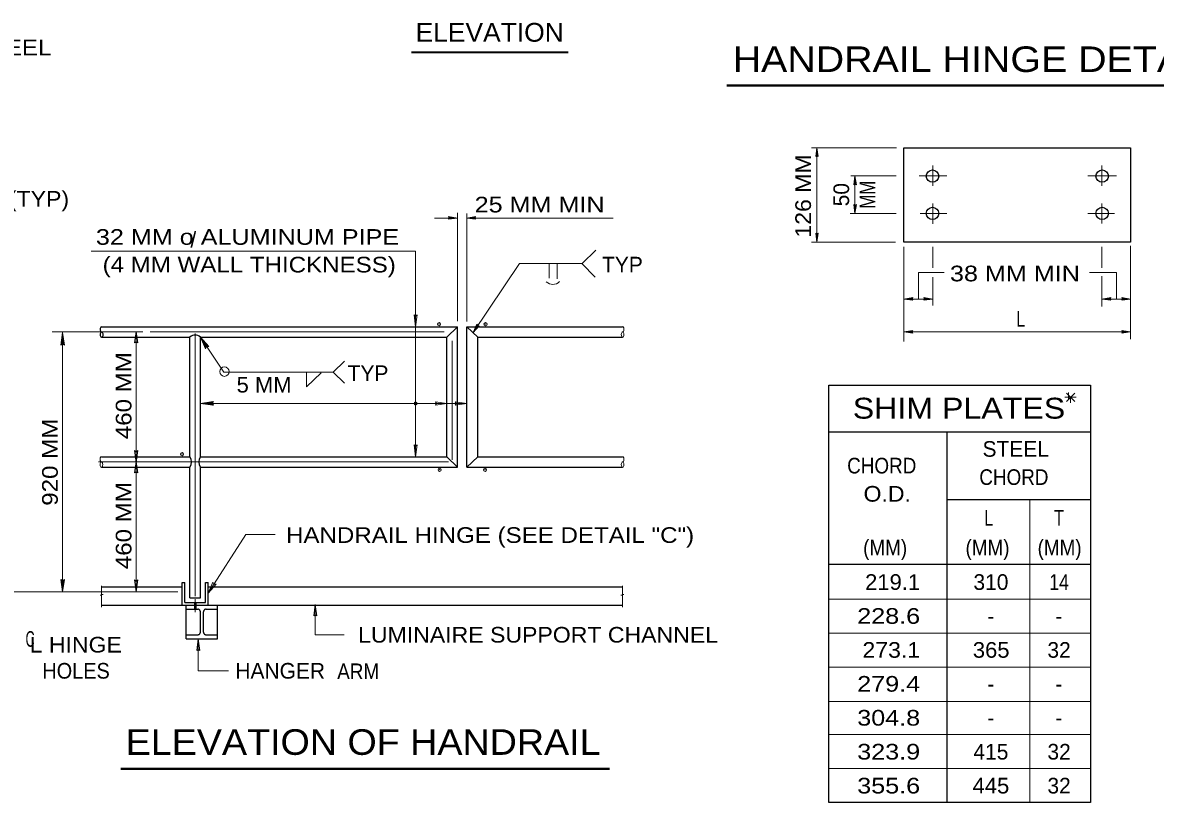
# Model space of a CAD drawing. Extents: x 312601.858 to 312602.699, y 144420.109 to 144420.704.
# Drawn here: x 312602.2633 to 312602.4801, y 144420.4036 to 144420.553 of the extents above; entities that cross this region are included whole.
import ezdxf
from ezdxf.enums import TextEntityAlignment as Align

# ---------------------------------------------------------------- set-up
doc = ezdxf.new("R2010")
doc.units = 0
doc.header["$LTSCALE"] = 0.0012
doc.header["$PDMODE"] = 32
doc.header["$PDSIZE"] = 0.0006
doc.linetypes.add('DOT_DASHED', pattern=[7.7, 5, -1.2, 0.3, -1.2])
doc.linetypes.add('LONG_DASHED', pattern=[7.5, 6, -1.5])
for name, color, linetype, lineweight in [('1', 7, 'Continuous', 13), ('2', 7, 'Continuous', 13), ('39', 7, 'Continuous', 13)]:
    doc.layers.add(name, color=color, linetype=linetype, lineweight=lineweight)

msp = doc.modelspace()

# ---------------------------------------------------------------- hatches: boundary and pattern name
at = {"layer": '2'}
msp.add_hatch(color=256, dxfattribs=at).paths.add_polyline_path([(312602.3388, 144420.48, 1), (312602.3382, 144420.48, 1)])
at = {"layer": '39'}
for points in [[(312602.4153, 144420.5275), (312602.4151, 144420.5273), (312602.4153, 144420.529), (312602.4156, 144420.5273)], [(312602.4153, 144420.5275), (312602.4151, 144420.5273), (312602.4153, 144420.529), (312602.4156, 144420.5273)], [(312602.4226, 144420.5221), (312602.4224, 144420.5219), (312602.4226, 144420.5236), (312602.4229, 144420.5219)], [(312602.4226, 144420.518), (312602.4229, 144420.5181), (312602.4226, 144420.5164), (312602.4224, 144420.5181)], [(312602.4226, 144420.518), (312602.4229, 144420.5181), (312602.4226, 144420.5164), (312602.4224, 144420.5181)], [(312602.345, 144420.5155), (312602.3448, 144420.5158), (312602.3465, 144420.5155), (312602.3448, 144420.5153)], [(312602.3499, 144420.5155), (312602.35, 144420.5153), (312602.3483, 144420.5155), (312602.35, 144420.5158)], [(312602.4153, 144420.5125), (312602.4156, 144420.5126), (312602.4153, 144420.5109), (312602.4151, 144420.5126)], [(312602.4153, 144420.5125), (312602.4156, 144420.5126), (312602.4153, 144420.5109), (312602.4151, 144420.5126)], [(312602.4336, 144420.5), (312602.4337, 144420.4998), (312602.432, 144420.5), (312602.4337, 144420.5003)], [(312602.436, 144420.5), (312602.4358, 144420.5003), (312602.4375, 144420.5), (312602.4358, 144420.4998)], [(312602.436, 144420.5), (312602.4358, 144420.5003), (312602.4375, 144420.5), (312602.4358, 144420.4998)], [(312602.4715, 144420.5), (312602.4716, 144420.4998), (312602.4699, 144420.5), (312602.4716, 144420.5003)], [(312602.4739, 144420.5), (312602.4737, 144420.5003), (312602.4754, 144420.5), (312602.4737, 144420.4998)], [(312602.3504, 144420.4949), (312602.3507, 144420.4949), (312602.3495, 144420.4936), (312602.3502, 144420.4952)], [(312602.4336, 144420.4937), (312602.4337, 144420.4935), (312602.432, 144420.4937), (312602.4337, 144420.494)], [(312602.4739, 144420.4937), (312602.4737, 144420.494), (312602.4754, 144420.4937), (312602.4737, 144420.4935)], [(312602.2709, 144420.4914), (312602.2706, 144420.4912), (312602.2709, 144420.4936), (312602.2713, 144420.4912)], [(312602.2709, 144420.4914), (312602.2706, 144420.4912), (312602.2709, 144420.4936), (312602.2713, 144420.4912)], [(312602.2985, 144420.4909), (312602.2983, 144420.4905), (312602.2973, 144420.4927), (312602.2989, 144420.4909)], [(312602.2995, 144420.48), (312602.2997, 144420.4797), (312602.2973, 144420.48), (312602.2997, 144420.4804)], [(312602.2996, 144420.48), (312602.2998, 144420.4797), (312602.2974, 144420.48), (312602.2998, 144420.4804)], [(312602.2709, 144420.4461), (312602.2713, 144420.4463), (312602.2709, 144420.4439), (312602.2706, 144420.4463)]]:
    msp.add_hatch(color=256, dxfattribs=at).paths.add_polyline_path(points)

# ---------------------------------------------------------------- linework, layer by layer
at = {"layer": '1'}
for p, q in [((312602.4143, 144420.529), (312602.4306, 144420.529)), ((312602.4153, 144420.529), (312602.4153, 144420.5109)), ((312602.4218, 144420.5236), (312602.4305, 144420.5236)), ((312602.4226, 144420.5236), (312602.4226, 144420.5164)), ((312602.3421, 144420.5155), (312602.3465, 144420.5155)), ((312602.3465, 144420.4958), (312602.3465, 144420.5165)), ((312602.3483, 144420.4957), (312602.3483, 144420.5164)), ((312602.3483, 144420.5155), (312602.3763, 144420.5155)), ((312602.4217, 144420.5164), (312602.4305, 144420.5164)), ((312602.2764, 144420.5092), (312602.3385, 144420.5092)), ((312602.3385, 144420.5092), (312602.3385, 144420.4947)), ((312602.4304, 144420.5109), (312602.4143, 144420.5109)), ((312602.432, 144420.4919), (312602.432, 144420.51)), ((312602.4375, 144420.51), (312602.4375, 144420.506)), ((312602.4699, 144420.51), (312602.4699, 144420.506)), ((312602.4754, 144420.5102), (312602.4754, 144420.4923)), ((312602.3641, 144420.504), (312602.3641, 144420.5068)), ((312602.3656, 144420.5039), (312602.3656, 144420.5068)), ((312602.4375, 144420.5042), (312602.4375, 144420.4988)), ((312602.4699, 144420.5044), (312602.4699, 144420.4986)), ((312602.432, 144420.5), (312602.4375, 144420.5)), ((312602.4699, 144420.5), (312602.4754, 144420.5)), ((312602.3385, 144420.4947), (312602.3385, 144420.4698)), ((312602.2689, 144420.4937), (312602.2863, 144420.4937)), ((312602.2709, 144420.4936), (312602.2709, 144420.4439)), ((312602.285, 144420.4937), (312602.285, 144420.4439)), ((312602.432, 144420.4937), (312602.4754, 144420.4937)), ((312602.4561, 144420.4616), (312602.4561, 144420.4036)), ((312602.2988, 144420.4437), (312602.306, 144420.4549)), ((312602.306, 144420.4549), (312602.3116, 144420.4549)), ((312602.254, 144420.4439), (312602.293, 144420.4439)), ((312602.4677, 144420.4425), (312602.4176, 144420.4425)), ((312602.4677, 144420.436), (312602.4176, 144420.436)), ((312602.2969, 144420.4349), (312602.2969, 144420.4288)), ((312602.3027, 144420.4288), (312602.2969, 144420.4288)), ((312602.4677, 144420.4295), (312602.4176, 144420.4295)), ((312602.4677, 144420.4229), (312602.4176, 144420.4229)), ((312602.4677, 144420.4166), (312602.4176, 144420.4166)), ((312602.4677, 144420.4101), (312602.4176, 144420.4101))]:
    msp.add_line(p, q, dxfattribs=at)
at = {"layer": '1', "lineweight": 25}
for p, q in [((312602.432, 144420.529), (312602.4754, 144420.529)), ((312602.432, 144420.5109), (312602.432, 144420.529)), ((312602.4754, 144420.529), (312602.4754, 144420.5109)), ((312602.4754, 144420.5109), (312602.432, 144420.5109)), ((312602.2784, 144420.4947), (312602.2938, 144420.4947)), ((312602.2937, 144420.4947), (312602.3465, 144420.4947)), ((312602.3465, 144420.4678), (312602.3465, 144420.4947)), ((312602.3483, 144420.4947), (312602.3781, 144420.4947)), ((312602.3483, 144420.4678), (312602.3483, 144420.4947)), ((312602.2784, 144420.4927), (312602.2953, 144420.4927)), ((312602.2953, 144420.4698), (312602.2953, 144420.4927)), ((312602.2973, 144420.4927), (312602.3445, 144420.4927)), ((312602.2973, 144420.4698), (312602.2973, 144420.4927)), ((312602.3445, 144420.4698), (312602.3445, 144420.4927)), ((312602.3504, 144420.4927), (312602.3781, 144420.4927)), ((312602.3504, 144420.4698), (312602.3504, 144420.4927)), ((312602.4176, 144420.4835), (312602.4677, 144420.4835)), ((312602.4176, 144420.4036), (312602.4176, 144420.4835)), ((312602.4176, 144420.4746), (312602.4677, 144420.4746)), ((312602.4402, 144420.4746), (312602.4402, 144420.4036)), ((312602.2784, 144420.4698), (312602.2953, 144420.4698)), ((312602.2784, 144420.4678), (312602.2953, 144420.4678)), ((312602.2953, 144420.4428), (312602.2953, 144420.4678)), ((312602.2973, 144420.4698), (312602.3445, 144420.4698)), ((312602.2973, 144420.4678), (312602.3465, 144420.4678)), ((312602.2973, 144420.4428), (312602.2973, 144420.4678)), ((312602.3483, 144420.4678), (312602.3781, 144420.4678)), ((312602.3504, 144420.4698), (312602.3781, 144420.4698)), ((312602.4402, 144420.4616), (312602.4677, 144420.4616)), ((312602.4176, 144420.4492), (312602.4677, 144420.4492)), ((312602.2784, 144420.4449), (312602.2938, 144420.4449)), ((312602.2938, 144420.4457), (312602.2943, 144420.4457)), ((312602.2938, 144420.4414), (312602.2938, 144420.4457)), ((312602.2943, 144420.4419), (312602.2943, 144420.4457)), ((312602.2983, 144420.4457), (312602.2988, 144420.4457)), ((312602.2983, 144420.4419), (312602.2983, 144420.4457)), ((312602.2988, 144420.4414), (312602.2988, 144420.4457)), ((312602.2988, 144420.4449), (312602.3781, 144420.4449)), ((312602.2943, 144420.4419), (312602.2983, 144420.4419)), ((312602.2953, 144420.4428), (312602.2973, 144420.4428)), ((312602.2962, 144420.4419), (312602.2962, 144420.4406)), ((312602.2964, 144420.4419), (312602.2964, 144420.4406)), ((312602.2784, 144420.4414), (312602.2998, 144420.4414)), ((312602.2946, 144420.4349), (312602.2946, 144420.4414)), ((312602.2998, 144420.4414), (312602.3781, 144420.4414)), ((312602.3006, 144420.4349), (312602.3006, 144420.4414)), ((312602.2946, 144420.4349), (312602.3006, 144420.4349))]:
    msp.add_line(p, q, dxfattribs=at)
at = {"layer": '1', "linetype": 'DOT_DASHED'}
for p, q in [((312602.4375, 144420.5217), (312602.4375, 144420.5256)), ((312602.4699, 144420.5217), (312602.4699, 144420.5256)), ((312602.4349, 144420.5236), (312602.4402, 144420.5236)), ((312602.4727, 144420.5236), (312602.4672, 144420.5236)), ((312602.4375, 144420.5183), (312602.4375, 144420.5144)), ((312602.4699, 144420.5183), (312602.4699, 144420.5145)), ((312602.4351, 144420.5164), (312602.4402, 144420.5164)), ((312602.4723, 144420.5164), (312602.4672, 144420.5164)), ((312602.2877, 144420.4937), (312602.344, 144420.4937)), ((312602.2963, 144420.4934), (312602.2963, 144420.4431)), ((312602.3455, 144420.492), (312602.3455, 144420.4692)), ((312602.2778, 144420.4688), (312602.3448, 144420.4688)), ((312602.2963, 144420.4425), (312602.2963, 144420.44))]:
    msp.add_line(p, q, dxfattribs=at)
at = {"layer": '1', "linetype": 'LONG_DASHED', "lineweight": 25}
for p, q in [((312602.2946, 144420.4406), (312602.2968, 144420.4406)), ((312602.2973, 144420.4362), (312602.2973, 144420.4401)), ((312602.2979, 144420.4362), (312602.2979, 144420.4401)), ((312602.2984, 144420.4406), (312602.3006, 144420.4406)), ((312602.2946, 144420.4357), (312602.2968, 144420.4357)), ((312602.2984, 144420.4357), (312602.3006, 144420.4357))]:
    msp.add_line(p, q, dxfattribs=at)
at = {"layer": '1'}
for points in [[(312602.3388, 144420.497), (312602.3385, 144420.4947), (312602.3382, 144420.497), (312602.3385, 144420.4967)], [(312602.2847, 144420.4916), (312602.285, 144420.4938), (312602.2853, 144420.4916), (312602.285, 144420.4918)], [(312602.3423, 144420.4803), (312602.3445, 144420.48), (312602.3423, 144420.4797), (312602.3425, 144420.48)], [(312602.3461, 144420.4803), (312602.3483, 144420.48), (312602.3461, 144420.4797), (312602.3463, 144420.48)], [(312602.3388, 144420.4721), (312602.3385, 144420.4698), (312602.3382, 144420.4721), (312602.3385, 144420.4718)], [(312602.2853, 144420.471), (312602.285, 144420.4687), (312602.2847, 144420.471), (312602.285, 144420.4707)], [(312602.2847, 144420.4667), (312602.285, 144420.4689), (312602.2853, 144420.4667), (312602.285, 144420.4669)], [(312602.2853, 144420.4462), (312602.285, 144420.4439), (312602.2847, 144420.4462), (312602.285, 144420.4459)], [(312602.3003, 144420.4454), (312602.2988, 144420.4437), (312602.2997, 144420.4458), (312602.2999, 144420.4454)], [(312602.319, 144420.4393), (312602.3193, 144420.4415), (312602.3196, 144420.4393), (312602.3193, 144420.4395)], [(312602.2966, 144420.4327), (312602.2969, 144420.4349), (312602.2972, 144420.4327), (312602.2969, 144420.4329)]]:
    msp.add_lwpolyline(points, close=True, dxfattribs=at)
at = {"layer": '1', "lineweight": 25}
msp.add_lwpolyline([(312602.4677, 144420.4835), (312602.4677, 144420.4036), (312602.4176, 144420.4036)], dxfattribs=at)
at = {"layer": '1'}
for points in [[(312602.2973, 144420.48), (312602.3445, 144420.48), (312602.3483, 144420.48)], [(312602.2784, 144420.4451), (312602.2784, 144420.4435), (312602.2784, 144420.441)], [(312602.3781, 144420.4451), (312602.3781, 144420.4435), (312602.3781, 144420.441)], [(312602.2784, 144420.4435), (312602.2787, 144420.4434), (312602.2781, 144420.4433), (312602.2784, 144420.4432)], [(312602.3781, 144420.4435), (312602.3784, 144420.4434), (312602.3778, 144420.4433), (312602.3781, 144420.4432)], [(312602.3193, 144420.4414), (312602.3193, 144420.4357), (312602.3248, 144420.4357)]]:
    msp.add_lwpolyline(points, dxfattribs=at)
at = {"layer": '1', "lineweight": 25}
for centre in [(312602.437475, 144420.523555), (312602.469945, 144420.523555), (312602.437475, 144420.516415), (312602.469945, 144420.516415)]:
    msp.add_circle(centre, 0.00119, dxfattribs=at)
at = {"layer": '1', "linetype": 'LONG_DASHED', "lineweight": 25}
for centre, start, end in [((312602.2968, 144420.4401), 0, 90), ((312602.2984, 144420.4401), 90, 180), ((312602.2968, 144420.4362), 270, 0), ((312602.2984, 144420.4362), 180, 270)]:
    msp.add_arc(centre, 0.0005, start, end, dxfattribs=at)
at = {"layer": '1'}
for centre in [(312602.378145, 144420.493195), (312602.278355, 144420.46829), (312602.378145, 144420.46829)]:
    msp.add_ellipse(centre, major_axis=(0, 0.00051), ratio=0.5, dxfattribs=at)
for centre, start_param, end_param in [((312602.378145, 144420.494215), 3.1415927, 6.411123), ((312602.278355, 144420.46931), 6.1552476, 9.424778), ((312602.378145, 144420.46931), 3.1415927, 6.411123)]:
    msp.add_ellipse(centre, major_axis=(0, 0.00051), ratio=0.5, start_param=start_param, end_param=end_param, dxfattribs=at)
for p in [(312602.343, 144420.4952), (312602.3519, 144420.4952), (312602.2938, 144420.4703), (312602.3431, 144420.4673), (312602.3518, 144420.4673)]:
    msp.add_point(p, dxfattribs=at)
at = {"layer": '2', "lineweight": 35}
msp.add_line((312602.3377, 144420.5473), (312602.3677, 144420.5473), dxfattribs=at)
at = {"layer": '2', "lineweight": 40}
for p, q in [((312602.3981, 144420.5409), (312602.5063, 144420.5409)), ((312602.2821, 144420.41), (312602.3756, 144420.41))]:
    msp.add_line(p, q, dxfattribs=at)
at = {"layer": '2'}
for p, q in [((312602.3704, 144420.5068), (312602.373, 144420.5094)), ((312602.3703, 144420.5068), (312602.3729, 144420.5042)), ((312602.4348, 144420.5051), (312602.4397, 144420.5051)), ((312602.4348, 144420.5), (312602.4348, 144420.5051)), ((312602.4675, 144420.5051), (312602.4727, 144420.5051)), ((312602.4727, 144420.5), (312602.4727, 144420.5051)), ((312602.3227, 144420.486), (312602.3249, 144420.4881)), ((312602.3227, 144420.486), (312602.3249, 144420.4839)), ((312602.464, 144420.4812), (312602.4628, 144420.4812)), ((312602.464, 144420.4811), (312602.4631, 144420.482)), ((312602.464, 144420.4813), (312602.4631, 144420.4804)), ((312602.4635, 144420.4809), (312602.4635, 144420.4821)), ((312602.4638, 144420.4811), (312602.4647, 144420.482)), ((312602.4638, 144420.4813), (312602.4647, 144420.4804)), ((312602.4638, 144420.4812), (312602.465, 144420.4812)), ((312602.4639, 144420.4813), (312602.4639, 144420.4801))]:
    msp.add_line(p, q, dxfattribs=at)
at = {"layer": '2', "lineweight": 25}
for p, q in [((312602.3445, 144420.4927), (312602.3465, 144420.4947)), ((312602.3504, 144420.4927), (312602.3483, 144420.4947)), ((312602.3465, 144420.4678), (312602.3445, 144420.4698)), ((312602.3483, 144420.4678), (312602.3504, 144420.4698))]:
    msp.add_line(p, q, dxfattribs=at)
at = {"layer": '2'}
for points in [[(312602.3495, 144420.4936), (312602.3584, 144420.5068), (312602.3704, 144420.5068)], [(312602.2973, 144420.4927), (312602.3018, 144420.486), (312602.3228, 144420.486)], [(312602.3176, 144420.486), (312602.3176, 144420.4832), (312602.3204, 144420.4859)]]:
    msp.add_lwpolyline(points, dxfattribs=at)
for centre, radius in [((312602.3019, 144420.4861), 0.0009), ((312602.3385, 144420.48), 0.0003)]:
    msp.add_circle(centre, radius, dxfattribs=at)
at = {"layer": '2', "lineweight": 25}
for centre, radius, start, end in [((312602.27865, 144420.4942), 0.000559, 116.56505, 243.43495), ((312602.27865, 144420.4932), 0.000559, 116.56505, 243.43495), ((312602.27815, 144420.4932), 0.000559, 296.56505, 63.43495), ((312602.2963, 144420.49165), 0.00145, 46.39718, 133.60282), ((312602.293783, 144420.4688), 0.001817, 326.60151, 33.39849), ((312602.298817, 144420.4688), 0.001817, 146.60151, 213.39849)]:
    msp.add_arc(centre, radius, start, end, dxfattribs=at)
at = {"layer": '2'}
msp.add_ellipse((312602.3648, 144420.504617), major_axis=(-0.001, -0.001517), ratio=0.983756, start_param=6.0844512, end_param=7.6472927, dxfattribs=at)
at = {"layer": '39'}
for points in [[(312602.4153, 144420.5275), (312602.4151, 144420.5273), (312602.4153, 144420.529), (312602.4156, 144420.5273)], [(312602.4153, 144420.5275), (312602.4151, 144420.5273), (312602.4153, 144420.529), (312602.4156, 144420.5273)], [(312602.4226, 144420.5221), (312602.4224, 144420.5219), (312602.4226, 144420.5236), (312602.4229, 144420.5219)], [(312602.4226, 144420.518), (312602.4229, 144420.5181), (312602.4226, 144420.5164), (312602.4224, 144420.5181)], [(312602.4226, 144420.518), (312602.4229, 144420.5181), (312602.4226, 144420.5164), (312602.4224, 144420.5181)], [(312602.345, 144420.5155), (312602.3448, 144420.5158), (312602.3465, 144420.5155), (312602.3448, 144420.5153)], [(312602.3499, 144420.5155), (312602.35, 144420.5153), (312602.3483, 144420.5155), (312602.35, 144420.5158)], [(312602.4153, 144420.5125), (312602.4156, 144420.5126), (312602.4153, 144420.5109), (312602.4151, 144420.5126)], [(312602.4153, 144420.5125), (312602.4156, 144420.5126), (312602.4153, 144420.5109), (312602.4151, 144420.5126)], [(312602.4336, 144420.5), (312602.4337, 144420.4998), (312602.432, 144420.5), (312602.4337, 144420.5003)], [(312602.436, 144420.5), (312602.4358, 144420.5003), (312602.4375, 144420.5), (312602.4358, 144420.4998)], [(312602.436, 144420.5), (312602.4358, 144420.5003), (312602.4375, 144420.5), (312602.4358, 144420.4998)], [(312602.4715, 144420.5), (312602.4716, 144420.4998), (312602.4699, 144420.5), (312602.4716, 144420.5003)], [(312602.4739, 144420.5), (312602.4737, 144420.5003), (312602.4754, 144420.5), (312602.4737, 144420.4998)], [(312602.3504, 144420.4949), (312602.3507, 144420.4949), (312602.3495, 144420.4936), (312602.3502, 144420.4952)], [(312602.4336, 144420.4937), (312602.4337, 144420.4935), (312602.432, 144420.4937), (312602.4337, 144420.494)], [(312602.4739, 144420.4937), (312602.4737, 144420.494), (312602.4754, 144420.4937), (312602.4737, 144420.4935)], [(312602.2709, 144420.4914), (312602.2706, 144420.4912), (312602.2709, 144420.4936), (312602.2713, 144420.4912)], [(312602.2709, 144420.4914), (312602.2706, 144420.4912), (312602.2709, 144420.4936), (312602.2713, 144420.4912)], [(312602.2985, 144420.4909), (312602.2983, 144420.4905), (312602.2973, 144420.4927), (312602.2989, 144420.4909)], [(312602.2995, 144420.48), (312602.2997, 144420.4797), (312602.2973, 144420.48), (312602.2997, 144420.4804)], [(312602.2996, 144420.48), (312602.2998, 144420.4797), (312602.2974, 144420.48), (312602.2998, 144420.4804)], [(312602.2709, 144420.4461), (312602.2713, 144420.4463), (312602.2709, 144420.4439), (312602.2706, 144420.4463)]]:
    msp.add_lwpolyline(points, close=True, dxfattribs=at)

# ---------------------------------------------------------------- texts
at = {"layer": '2'}
for s, height, width, p in [('ELEVATION', 0.0036, 1.05, (312602.3385, 144420.5493)), ('STAINLESS STEEL', 0.003, 1.15, (312602.2275, 144420.5467)), ('HANDRAIL HINGE DETAIL "C"', 0.0049, 1.15, (312602.3992, 144420.5435)), ('32 MM o ALUMINUM PIPE', 0.003, 1.2, (312602.2773, 144420.5104)), ('SHIM PLATES', 0.004, 1.15, (312602.4222, 144420.4771)), ('L', 0.003, 0.75, (312602.4474, 144420.4566)), ('T', 0.003, 0.8, (312602.4607, 144420.4566)), ('HANDRAIL HINGE (SEE DETAIL "C")', 0.003, 1.15, (312602.3137, 144420.4533)), ('LUMINAIRE SUPPORT CHANNEL', 0.003, 1.1, (312602.3275, 144420.4342)), ('ARM', 0.003, 0.9, (312602.3235, 144420.4272)), ('ELEVATION OF HANDRAIL', 0.0049, 1.1, (312602.283, 144420.4127))]:
    msp.add_text(s, height=height, dxfattribs=dict(at, width=width)).set_placement(p)
for s, width, p in [('126 MM', 1.1, (312602.4142, 144420.51975)), ('MM', 0.8, (312602.4265, 144420.52)), ('460 MM', 1.15, (312602.2841, 144420.4815)), ('920 MM', 1.15, (312602.27, 144420.46875)), ('460 MM', 1.15, (312602.2841, 144420.4566))]:
    msp.add_text(s, height=0.003, rotation=90, dxfattribs=dict(at, width=width)).set_placement(p, align=Align.CENTER)
msp.add_text('50', height=0.003, rotation=90, dxfattribs=at).set_placement((312602.4215, 144420.52), align=Align.CENTER)
for s, width, p in [('SIGN HANGER (TYP)', 1.1, (312602.25035, 144420.5177)), ('25 MM MIN', 1.2, (312602.36225, 144420.5166)), ('(4 MM WALL THICKNESS)', 1.15, (312602.30665, 144420.5051)), ('38 MM MIN', 1.2, (312602.45325, 144420.5034)), ('L', 0.75, (312602.45435, 144420.4947)), ('5 MM', 1.05, (312602.3095, 144420.4821)), ('CHORD', 0.9, (312602.42775, 144420.4666)), ('CHORD', 0.9, (312602.45305, 144420.4644)), ('O.D.', 1.1, (312602.4288, 144420.4612)), ('(MM)', 0.9, (312602.4284, 144420.4509)), ('(MM)', 0.9, (312602.448, 144420.4509)), ('(MM)', 0.9, (312602.4618, 144420.4509)), ('14', 0.85, (312602.4617, 144420.4443)), ('C', 0.6, (312602.2647, 144420.4334)), ('L HINGE', 1.1, (312602.27345, 144420.4323)), ('365', 1.05, (312602.4487, 144420.4313)), ('HOLES', 0.95, (312602.2735, 144420.4273)), ('445', 1.05, (312602.44865, 144420.4053))]:
    msp.add_text(s, height=0.003, dxfattribs=dict(at, width=width)).set_placement(p, align=Align.CENTER)
for s, p in [('/', (312602.29595, 144420.5099)), ('TYP', (312602.3781, 144420.5051)), ('TYP', (312602.3294, 144420.4843)), ('STEEL', (312602.4534, 144420.4698)), ('310', (312602.44865, 144420.4443)), ('-', (312602.44865, 144420.4378)), ('-', (312602.46165, 144420.4378)), ('32', (312602.4617, 144420.4313)), ('-', (312602.44865, 144420.4248)), ('-', (312602.46165, 144420.4248)), ('-', (312602.44865, 144420.4183)), ('-', (312602.46165, 144420.4183)), ('415', (312602.44865, 144420.4118)), ('32', (312602.4617, 144420.4118)), ('32', (312602.4617, 144420.4053))]:
    msp.add_text(s, height=0.003, dxfattribs=at).set_placement(p, align=Align.CENTER)
for s, width, p in [('219.1', 1.05, (312602.4351, 144420.4443)), ('228.6', 1.2, (312602.4351, 144420.4378)), ('273.1', 1.1, (312602.4351, 144420.4313)), ('279.4', 1.2, (312602.4351, 144420.4248)), ('304.8', 1.2, (312602.4351, 144420.4183)), ('323.9', 1.2, (312602.4351, 144420.4118)), ('355.6', 1.2, (312602.4351, 144420.4053))]:
    msp.add_text(s, height=0.003, dxfattribs=dict(at, width=width)).set_placement(p, align=Align.RIGHT)
msp.add_text('HANGER', height=0.003, dxfattribs=at).set_placement((312602.304, 144420.4273))

doc.saveas('drawing.dxf')
